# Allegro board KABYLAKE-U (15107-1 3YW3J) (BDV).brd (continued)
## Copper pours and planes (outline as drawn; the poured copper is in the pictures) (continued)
CAGND on TOP: 38.72,23.16 38.64,23.24 38.64,24.77 38.51,24.89 34.83,24.89 34.7,25.02 34.7,26.67 33.94,27.43 33.94,28.07 34.2,28.32 36.61,28.32 36.86,28.07 37.75,28.07 38.26,28.57 38.26,29.34 38.39,29.46 39.4,29.46 39.53,29.34 39.53,27.94 39.28,27.69 39.28,23.24 39.2,23.16 ; 9 cut-outs
CHG_AGND on TOP: 40.67,43.18 40.17,43.69 40.17,44.07 40.42,44.32 40.42,45.21 40.8,45.21 40.93,45.09 40.93,44.32 41.31,43.94 43.21,43.94 43.85,44.58 43.85,46.35 44.1,46.61 45.75,46.61 45.88,46.74 45.88,47.12 46.01,47.24 46.64,47.24 46.77,47.12 46.77,43.69 46.64,43.56 43.21,43.56 42.83,43.18 ; 8 cut-outs
CORE_PLLVDD on TOP: 95.74,101.6 95.61,101.73 95.61,102.57 95.79,102.74 101.13,102.74 101.25,102.62 101.25,101.85 101,101.6 ; 2 cut-outs
DC_19V on TOP: 62.64,31.75 62.39,32 62.39,36.96 63.03,37.59 71.28,37.59 71.41,37.47 71.41,36.45 71.28,36.32 69.88,36.32 69.5,35.94 69.5,31.88 69.38,31.75 ; 4 cut-outs
DC_19V on BOTTOM: 62.77,34.29 62.39,34.67 62.39,35.18 61.37,36.2 61.37,38.23 66.58,38.23 67.22,37.59 71.03,37.59 71.28,37.34 71.28,35.05 70.52,34.29
DCBATOUT on TOP: 147.23,31.11 146.97,31.37 146.97,34.42 148.12,35.56 149.51,35.56 149.89,35.18 149.89,34.8 149.51,34.42 148.24,34.42 147.99,34.16 147.99,32.51 148.24,32.26 148.37,32.26 148.75,31.88 148.75,31.24 148.62,31.11
DCBATOUT on TOP: 34.32,79.12 33.94,79.5 33.94,81.92 29.88,85.98 29.88,132.21 28.23,133.86 16.04,133.86 15.78,134.11 15.78,138.81 16.04,139.06 25.18,139.06 25.56,139.45 25.56,140.97 25.62,141.03 32.68,141.03 32.7,141.02 32.7,136.88 35.09,134.49 35.09,89.41 39.28,85.22 39.28,79.38 39.02,79.12
DCBATOUT on TOP: 40.04,72.9 39.78,73.15 39.78,74.93 39.53,75.18 39.53,75.69 39.28,75.95 39.28,76.58 39.4,76.71 42.32,76.71 43.09,75.95 43.09,73.03 42.96,72.9
DCBATOUT on TOP: 62.64,43.31 62.64,44.58 62.52,44.7 57.69,44.7 57.44,44.96 51.98,44.96 46.9,50.04 41.31,50.04 41.18,50.16 41.18,54.23 41.31,54.36 49.69,54.36 54.01,50.04 63.28,50.04 64.8,48.51 97.95,48.51 98.33,48.13 98.33,45.97 96.17,43.81 71.79,43.81 71.28,43.31
DCBATOUT on TOP: 150.78,45.09 150.66,45.21 150.66,47.12 150.78,47.24 151.67,47.24 151.8,47.12 151.8,45.34 151.54,45.09
DCBATOUT on TOP: 106.71,61.85 106.21,62.36 106.21,67.31 106.59,67.69 120.43,67.69 121.95,69.22 122.97,69.22 126.4,72.64 126.4,73.79 126.78,74.17 126.78,83.06 132.24,83.06 132.37,82.93 142.02,82.93 142.15,82.8 142.15,79.25 139.35,76.45 135.54,76.45 122.59,63.5 111.92,63.5 110.27,61.85
DCBATOUT on TOP: 20.23,165.99 19.97,166.24 19.97,172.09 20.23,172.34 26.83,172.34 27.34,171.83 27.34,166.12 27.21,165.99
DCBATOUT on TOP: 46.01,37.08 45.88,37.21 45.88,40.39 46.01,40.51 47.02,40.51 47.28,40.77 52.74,40.77 52.99,40.51 52.99,39.5 52.87,39.37 49.18,39.37 48.93,39.12 48.93,38.61 48.8,38.48 47.91,38.48 47.53,38.1 47.53,37.21 47.4,37.08 ; 1 cut-out
DCBATOUT on BOTTOM: 63.53,45.21 62.39,46.35 57.44,46.35 56.42,47.37 52.74,47.37 48.67,51.44 45.25,51.44 44.86,51.05 44.86,50.29 44.48,49.91 41.31,49.91 41.18,50.04 41.18,56.26 41.31,56.39 44.99,56.39 45.25,56.64 45.25,64.64 43.59,66.29 43.59,72.64 43.21,73.03 40.04,73.03 39.78,73.28 39.78,74.93 39.53,75.18 39.53,75.56 39.09,76.01 39.02,76.01 35.21,79.82 35.21,82.04 35.47,82.3 42.96,82.3 50.33,74.93 50.33,71.63 49.82,71.12 49.82,66.17 50.45,65.53 50.45,53.21 54.33,49.34 56.99,49.34 58.07,48.26 64.55,48.26 65.06,47.75 65.06,45.47 64.8,45.21 ; 3 cut-outs
DCBATOUT on BOTTOM: 77.76,220.85 77.5,221.11 77.5,224.41 77.76,224.66 81.69,224.66 81.82,224.54 81.82,220.85
DCBATOUT on BOTTOM: 122.84,74.8 121.19,76.45 121.19,78.99 121.57,78.99 124.11,76.45 126.65,76.45 126.78,76.58 126.78,83.06 132.24,83.06 132.37,82.93 132.37,81.92 132.62,81.66 138.08,81.66 138.08,79.12 134.27,75.31 127.67,75.31 127.16,74.8 ; 2 cut-outs
DCBATOUT on BOTTOM: 14.64,136.14 14,136.78 14,149.48 12.99,150.5 12.99,168.91 14.89,170.81 14.89,186.69 14.38,187.2 14.38,201.8 14.77,202.18 14.77,206.38 15.02,206.63 15.02,211.23 17.31,213.51 17.31,218.57 20.48,221.74 33.69,221.74 35.47,223.52 56.04,223.52 56.55,223.01 59.98,223.01 60.23,222.76 60.23,221.23 60.1,221.11 55.41,221.11 55.02,221.49 36.48,221.49 34.7,219.71 21.62,219.71 19.46,217.55 19.46,216.41 19.72,216.15 27.21,216.15 27.59,216.53 34.96,216.53 35.21,216.28 35.21,213.23 35.09,213.11 33.94,213.11 32.93,214.12 28.61,214.12 28.35,213.87 21.39,213.87 17.57,210.05 17.57,209.64 17.56,209.63 17.56,188.85 18.07,188.34 25.69,188.34 28.1,190.75 33.18,190.75 34.45,192.02 45.88,192.02 46.01,191.9 46.01,189.74 45.75,189.48 41.69,189.48 39.53,187.32 28.86,187.32 26.7,185.17 18.7,185.17 18.45,184.91 18.45,171.83 19.08,171.2 24.8,171.2 25.05,170.94 25.05,169.93 25.43,169.54 27.08,169.54 27.34,169.29 27.34,166.12 27.21,165.99 21.24,165.99 19.59,164.34 19.59,136.27 19.46,136.14
DCBATOUT on BOTTOM: 122.08,22.99 121.7,23.37 117.38,23.37 116.81,23.94 108.55,23.94 107.86,24.64 106.21,24.64 104.94,25.91 104.94,29.34 102.9,31.37 102.9,35.05 101.95,36 101.95,43.75 99.98,45.72 95.03,45.72 94.65,46.1 94.65,49.4 98.2,52.96 98.2,60.71 102.65,65.15 109.38,65.15 109.89,64.64 109.89,62.23 109.51,61.85 106.08,61.85 104.17,59.94 104.17,52.07 105.06,51.18 105.06,47.37 110.36,42.08 110.36,29.76 111.67,28.45 116.11,28.45 116.49,28.83 121.45,28.83 121.83,29.21 122.84,29.21 123.99,30.35 127.41,30.35 128.05,30.99 133.38,30.99 133.51,31.11 140.62,31.11 141.89,32.38 148.75,32.38 148.88,32.26 148.88,28.7 148.62,28.45 145.32,28.45 145.07,28.19 141.38,28.19 141.13,27.94 131.61,27.94 131.48,27.81 131.48,26.54 131.22,26.29 127.54,26.29 125.26,24 124.62,24 123.6,22.99
DCBATOUT on L3: 78.01,223.39 78.39,223.01 78.39,220.98 78.27,220.85 76.11,220.85 75.6,221.36 60.36,221.36 60.1,221.11 57.95,221.11 57.44,221.62 57.44,222.76 57.56,222.88 58.33,222.88 58.83,223.39
DCBATOUT_1D35V_VGA on TOP: 117.71,73.1 117.71,73.56 117.48,73.79 117,73.79 117,77.47 116.75,77.72 116.75,79.88 116.87,80.01 119.16,80.01 119.79,79.38 119.79,78.11 119.67,77.98 118.14,77.98 118.04,77.88 118.04,76.58 118.5,76.58 118.52,76.56 118.52,73.79 118.02,73.79 118.02,73.1
DCBATOUT_1D35V_VGA on BOTTOM: 117.18,73.79 117.08,73.89 117.08,76.89 116.75,77.22 116.75,79.88 116.87,80.01 119.16,80.01 119.92,79.25 120.43,79.25 120.56,79.12 120.56,76.33 119.92,76.33 119.54,75.95 119.54,74.04 119.29,73.79 ; 2 cut-outs
DCBATOUT_RT6575_3V on TOP: 128.18,22.61 127.92,22.86 127.92,27.3 128.18,27.56 132.11,27.56 132.37,27.3 132.37,22.73 132.24,22.61
DCBATOUT_RT6575_3V on BOTTOM: 129.57,19.43 129.45,19.56 129.45,20.7 127.8,22.35 127.8,25.65 127.92,25.78 131.61,25.78 131.86,26.04 131.86,27.43 131.99,27.56 133,27.56 133.13,27.43 133.13,19.56 133,19.43 ; 1 cut-out
DCBATOUT_RT6575_5V on TOP: 143.42,22.61 143.29,22.73 143.29,27.43 143.42,27.56 147.23,27.56 147.61,27.18 147.61,25.27 147.23,24.89 147.23,22.86 146.97,22.61
DCBATOUT_RT6575_5V on BOTTOM: 143.92,19.43 143.92,22.35 143.54,22.73 143.54,27.81 148.88,27.81 149,27.69 149,24.51 148.62,24.13 147.48,24.13 147.23,23.88 147.23,19.43 ; 2 cut-outs
DCBATOUT_VCCGTA on TOP: 36.99,209.04 36.74,209.3 36.74,215.01 39.78,218.06 47.53,218.06 47.53,212.6 47.28,212.34 41.56,212.34 38.9,209.68 38.9,209.3 38.64,209.04
DCBATOUT_VCCGTA on BOTTOM: 35.97,212.22 35.72,212.47 35.72,216.79 35.34,217.17 27.72,217.17 27.72,219.33 27.85,219.46 37.88,219.46 38.39,218.95 43.85,218.95 43.98,218.82 43.98,215.39 43.59,215.01 41.94,215.01 41.05,214.12 41.05,212.47 40.8,212.22 ; 2 cut-outs
DCBATOUT_VCCGTB on TOP: 34.58,192.41 34.45,192.53 34.45,197.74 34.58,197.87 41.94,197.87 42.32,198.25 47.53,198.25 47.66,198.12 47.66,192.53 47.53,192.41
DCBATOUT_VCCGTB on BOTTOM: 34.58,192.41 34.32,192.66 34.32,197.74 34.45,197.87 41.44,197.87 43.34,195.96 45.88,195.96 46.13,195.71 46.13,192.66 45.88,192.41
DCBATOUT_VCCSA on TOP: 32.16,164.47 32.04,164.59 32.04,164.97 31.28,165.74 29.5,165.74 29.24,165.99 28.1,165.99 27.97,166.12 27.97,171.45 28.1,171.58 34.58,171.58 34.83,171.32 34.83,164.47
DCBATOUT_VCCSA on BOTTOM: 32.16,164.47 32.04,164.59 32.04,164.97 31.28,165.74 29.5,165.74 29.24,165.99 28.1,165.99 27.97,166.12 27.97,169.42 30.13,171.58 34.58,171.58 34.83,171.32 34.83,164.47
DCBATOUT_VCORE on TOP: 19.34,172.97 19.21,173.1 19.21,178.44 19.46,178.69 33.05,178.69 33.05,173.23 32.93,173.1 25.94,173.1 25.81,172.97
DCBATOUT_VCORE on BOTTOM: 19.46,171.83 19.21,172.09 19.21,177.8 26.58,177.8 27.47,178.69 33.05,178.69 33.05,173.23 32.93,173.1 27.47,173.1 27.15,172.78 27.15,172.15 26.83,171.83
DDR_VDDQ on TOP: 91.16,207.9 91.16,211.2 91.28,211.33 92.87,211.33 93,211.46 93,214.5 93.51,215.01 102.65,215.01 103.28,214.38 103.28,208.41 102.78,207.9
DDR_VDDQ on TOP: 112.56,99.06 112.43,99.19 112.43,100.2 111.41,101.22 111.41,102.62 111.29,102.74 111.29,106.17 111.41,106.3 113.95,106.3 114.08,106.17 114.08,102.11 114.21,101.98 116.11,101.98 116.11,101.73 117,100.84 117,99.44 116.62,99.06
DDR_VDDQ on TOP: 159.29,168.28 159.16,168.4 159.16,169.04 157.2,171.01 155.93,171.01 155.74,171.2 155.74,172.34 155.86,172.47 157.26,172.47 157.39,172.59 158.66,172.59 159.67,171.58 159.67,169.29 159.8,169.16 159.8,168.4 159.67,168.28 ; 2 cut-outs
DDR_VDDQ on BOTTOM: outline of 112 points within 90.33,131.44 156.5,211.71 ; 87 cut-outs
FB_PLLAVDD on L3: 78.14,94.87 78.14,100.58 78.01,100.71 76.61,100.71 76.49,100.58 76.49,100.2 76.61,100.08 77.25,100.08 77.38,99.95 77.38,95.12 77.25,95 76.61,95 76.49,94.87 76.49,94.36 76.61,94.23 81.19,94.23 81.44,93.98 81.44,93.6 81.57,93.47 81.95,93.47 82.08,93.6 82.08,94.49 81.82,94.74 78.27,94.74
GPU_1D05V on TOP: 105.7,99.06 105.7,105.03 106.33,105.66 106.33,106.17 106.46,106.3 107.22,106.3 108.49,105.03 108.49,103.76 109,103.25 110.9,103.25 110.9,100.58 111.16,100.33 111.16,99.19 111.03,99.06 ; 3 cut-outs
ISW_1 on BOTTOM: 41.05,34.42 40.8,34.67 40.8,38.61 40.81,38.62 40.81,39.05 41,39.24 44.1,39.24 44.61,38.73 44.61,34.8 44.48,34.67 42.96,34.67 42.71,34.42
LX on TOP: 33.82,31.24 33.69,31.37 33.69,37.85 33.94,38.1 38.26,38.1 38.64,37.72 38.64,31.62 38.26,31.24
LX on BOTTOM: 33.48,30.28 32.8,30.96 32.8,34.67 32.93,34.8 35.34,34.8 35.47,34.92 35.47,37.47 36.23,38.23 36.23,39.88 37.37,39.88 37.5,39.75 37.5,38.23 37.63,38.1 38.26,38.1 38.64,37.72 38.64,32.51 38.51,32.38 35.72,32.38 35.54,32.21 35.54,30.4 35.42,30.28
MCT_R on TOP: 60.23,9.65 60.1,9.78 60.1,14.1 60.23,14.22 62.52,14.22 62.77,13.97 63.53,13.97 63.79,14.22 63.79,16.89 66.2,16.89 66.2,13.92 65.06,12.78 65.06,10.54 64.42,9.91 62.77,9.91 62.52,9.65 ; 2 cut-outs
MEM_VTT on BOTTOM: 104.68,193.04 99.47,198.25 95.03,198.25 90.84,202.44 90.84,209.17 90.97,209.3 92.11,209.3 92.36,209.04 92.36,202.56 95.66,199.26 100.11,199.26 105.44,193.93 105.44,193.17 105.32,193.04
MEM_VTT on BOTTOM: 141,123.44 140.88,123.57 140.88,123.7 141,123.83 141,126.36 141.13,126.49 141.77,126.49 141.89,126.62 141.89,127.13 142.02,127.25 142.53,127.25 142.78,127 142.78,126.62 143.04,126.36 144.81,126.36 145.58,127.13 149.77,127.13 150.66,126.24 152.05,126.24 152.18,126.36 152.18,126.75 152.31,126.87 152.56,126.87 152.69,126.75 152.69,126.36 152.94,126.11 154.21,126.11 154.34,125.98 154.34,125.22 154.08,124.97 152.18,124.97 151.8,125.35 147.89,125.35 147.25,125.98 145.7,125.98 145.19,125.48 143.29,125.48 142.84,125.03 142.84,123.76 142.53,123.44 ; 5 cut-outs
Net_8 on BOTTOM (solid shape): 118.14,114.05 118.14,108.2 117.13,107.19 115.48,107.19 115.48,114.3 117.89,114.3
P3P3V on BOTTOM: 60.87,57.78 59.72,58.93 57.18,58.93 57.06,59.05 57.06,60.71 56.93,60.83 56.04,60.83 55.02,61.85 54.39,61.85 54.26,61.98 54.26,62.74 54.39,62.87 55.41,62.87 56.17,62.1 60.74,62.1 60.99,61.85 60.99,60.83 61.76,60.07 61.76,57.91 61.63,57.78 ; 4 cut-outs
PEX_PLLVDD_GPU on BOTTOM: 82.46,106.05 81.69,106.81 81.69,108.08 81.31,108.46 81.31,110.11 81.06,110.36 80.3,110.36 80.17,110.49 80.17,111.63 80.04,111.76 77.63,111.76 77.5,111.89 77.5,112.78 77.63,112.9 82.46,112.9 82.58,112.78 82.58,111 82.2,110.62 82.2,109.09 82.46,108.84 82.46,106.81 82.84,106.43 82.84,106.17 82.71,106.05 ; 1 cut-out
PWR_1D0V_PHASE on TOP: 37.75,144.4 37.63,144.53 37.63,148.72 37.37,148.97 37.12,148.97 36.99,149.1 36.99,150.88 36.74,151.13 35.47,151.13 35.34,151.26 35.34,156.72 35.47,156.84 42.58,156.84 42.83,156.59 42.83,147.07 42.71,146.94 41.31,146.94 41.18,146.81 41.18,144.53 41.05,144.4
PWR_1D0V_PHASE on BOTTOM: 37.75,144.4 37.63,144.53 37.63,148.72 37.37,148.97 37.12,148.97 36.99,149.1 36.99,150.88 36.74,151.13 33.94,151.13 33.82,151.26 33.82,156.72 33.94,156.84 42.58,156.84 42.83,156.59 42.83,147.07 42.71,146.94 41.31,146.94 41.18,146.81 41.18,144.53 41.05,144.4
PWR_1D35V_VGA on TOP: 100.49,70.36 100.49,76.2 107.73,76.2 107.98,75.95 107.98,70.48 107.86,70.36
PWR_2D5V_VIN on BOTTOM: 130.72,202.56 130.59,202.69 130.59,203.33 130.72,203.45 132.37,203.45 132.62,203.71 132.62,208.03 132.49,208.15 132.49,211.84 132.62,211.96 136.94,211.96 137.07,211.84 137.07,207.9 136.81,207.65 135.67,207.65 135.42,207.39 135.42,202.95 135.03,202.56
PWR_2D5V_VOUT on BOTTOM: 135.92,198.75 135.8,198.88 135.8,204.72 138.34,204.72 139.23,205.61 140.75,205.61 140.88,205.49 140.88,198.88 140.75,198.75 ; 3 cut-outs
PWR_3D3V_LG2 on BOTTOM: 136.3,21.21 136.3,22.23 137.7,22.23 137.83,22.1 137.83,21.34 137.7,21.21
PWR_3D3V_PH2 on TOP: 131.22,15.88 130.97,16.13 130.97,20.45 131.1,20.57 136.18,20.57 136.43,20.32 136.43,16 136.3,15.88
PWR_3D3V_PH2 on BOTTOM: 137.45,14.1 136.18,15.37 130.08,15.37 129.83,15.62 129.83,16.51 129.95,16.64 130.46,16.64 130.59,16.76 130.59,18.8 130.72,18.92 133.64,18.92 133.76,19.05 133.76,20.57 133.89,20.7 137.19,20.7 137.19,15.75 137.32,15.62 138.84,15.62 138.97,15.49 138.97,14.22 138.84,14.1
PWR_5V_HG1 on BOTTOM: 143.92,16.89 143.54,17.27 143.54,18.8 143.67,18.92 144.81,18.92 144.81,17.02 144.69,16.89
PWR_5V_LG1 on BOTTOM: 141.89,21.21 141.89,22.23 143.16,22.23 143.29,22.1 143.29,21.34 143.16,21.21
PWR_5V_PH1 on TOP: 137.32,14.61 137.19,14.73 137.19,16 137.32,16.13 138.84,16.13 139.48,16.76 139.48,20.45 139.61,20.57 146.59,20.57 146.72,20.45 146.72,15.75 146.46,15.49 139.86,15.49 138.97,14.61
PWR_5V_PH1 on BOTTOM: 139.86,15.49 139.48,15.88 139.48,20.57 139.61,20.7 142.78,20.7 142.91,20.57 142.91,17.02 143.42,16.51 144.94,16.51 145.19,16.76 145.19,17.78 145.07,17.91 145.07,18.92 146.72,18.92 146.72,15.75 146.46,15.49
PWR_CHG_BT_LR on TOP: 37.37,60.45 37.24,60.58 37.24,63.88 37.37,64.01 38.9,64.01 38.9,65.28 39.02,65.41 42.96,65.41 43.09,65.28 43.09,63.75 43.21,63.63 43.85,63.63 43.98,63.5 43.98,60.58 43.85,60.45
PWR_CHG_PHASE on TOP: 37.12,55.12 36.99,55.24 36.99,59.18 37.24,59.44 43.59,59.44 43.72,59.31 43.72,55.24 43.59,55.12
PWR_CHG_PHASE on BOTTOM: 37.12,55.12 36.99,55.24 36.99,60.25 37.85,61.11 42.27,61.11 43.72,59.66 43.72,56.77 40.93,56.77 40.55,56.39 40.55,55.24 40.42,55.12
PWR_DCBATOUT_1D0V on TOP: 25.69,141.86 25.56,141.99 25.56,144.4 27.72,146.56 29.37,146.56 29.75,146.94 29.75,148.59 29.88,148.72 31.78,148.72 32.42,148.08 36.48,148.08 36.61,147.96 36.61,142.49 36.36,142.24 33.31,142.24 32.93,141.86
PWR_DCBATOUT_1D0V on BOTTOM: 25.69,141.86 25.56,141.99 25.56,144.4 27.72,146.56 27.72,148.84 27.59,148.97 27.59,149.99 27.85,150.24 30.89,150.24 31.02,150.11 31.02,149.73 31.15,149.61 31.91,149.61 32.04,149.48 32.04,148.59 32.42,148.21 37.37,148.21 37.37,142.75 37.24,142.62 33.18,142.62 32.42,141.86 ; 1 cut-out
PWR_DCBATOUT_VDDQ on TOP: 87.66,216.92 87.28,217.3 86.01,217.3 85.76,217.55 85.76,219.2 84.36,220.6 84.36,223.65 89.57,223.65 89.82,223.39 89.82,217.17 89.57,216.92 ; 2 cut-outs
PWR_DCBATOUT_VDDQ on BOTTOM: 82.71,219.84 82.33,220.22 82.33,224.41 83.47,224.41 84.11,223.77 89.7,223.77 90.08,224.16 90.08,225.17 90.2,225.3 95.66,225.3 95.92,225.04 95.92,219.96 95.79,219.84
PWR_VCCGT_SWA on TOP: 44.1,205.87 44.1,211.46 47.66,211.46 47.91,211.71 47.91,216.28 54.01,216.28 54.26,216.03 54.26,206.25 53.88,205.87
PWR_VCCGT_SWA on BOTTOM: 44.1,205.87 44.1,211.46 45.75,211.46 46.01,211.71 46.01,214.38 47.91,216.28 54.01,216.28 54.26,216.03 54.26,206.25 53.88,205.87
PWR_VCCGT_SWB on TOP: 47.91,192.66 47.91,196.47 49.69,196.47 49.82,196.6 49.82,199.01 49.56,199.26 44.23,199.26 44.1,199.39 44.1,204.85 54.14,204.85 54.26,204.72 54.26,192.91 54.01,192.66
PWR_VCCGT_SWB on BOTTOM: 48.17,192.66 47.91,192.91 47.91,195.45 46.52,196.85 46.52,199.14 46.39,199.26 44.23,199.26 44.1,199.39 44.1,204.85 54.14,204.85 54.26,204.72 54.26,192.91 54.01,192.66
PWR_VCCSA_DRVH on TOP: 36.74,166.75 36.61,166.88 35.34,166.88 35.34,167.77 35.47,167.89 37.12,167.89 37.37,167.64 37.37,167 37.12,166.75
PWR_VCCSA_DRVL on TOP: 31.28,160.02 31.02,160.27 31.02,160.78 31.15,160.91 33.05,160.91 33.05,160.15 32.93,160.02
PWR_VCCSA_PH on TOP: 33.56,160.02 33.56,163.32 35.21,163.32 35.34,163.45 35.34,166.62 36.36,166.62 36.61,166.37 37.37,166.37 38.01,167 39.4,167 39.53,166.88 39.53,160.15 39.4,160.02
PWR_VCCSA_PH on BOTTOM: 35.47,160.02 35.34,160.15 35.34,166.62 36.36,166.62 36.61,166.37 37.37,166.37 38.01,167 39.4,167 39.53,166.88 39.53,160.15 39.4,160.02
PWR_VCORE_SW on TOP: 33.43,173.61 33.31,173.74 33.31,176.91 35.09,176.91 35.21,177.04 35.21,179.58 35.09,179.71 29.5,179.71 29.5,187.58 29.62,187.71 30.64,187.71 30.77,187.58 30.77,185.42 30.89,185.29 38.64,185.29 39.02,184.91 39.02,175.26 38.9,175.13 38.64,175.13 38.51,175.01 38.51,173.99 38.13,173.61
PWR_VCORE_SW on BOTTOM: 33.31,174.88 33.31,178.18 35.09,178.18 35.21,178.31 35.21,179.58 35.09,179.71 29.5,179.71 29.5,185.17 29.62,185.29 38.64,185.29 39.02,184.91 39.02,175.26 38.64,174.88
PWR_VDDQ_PH on TOP: 93.38,215.65 93,216.03 93,220.73 93.38,221.11 103.41,221.11 103.79,220.73 103.79,216.66 102.78,215.65
PWR_VDDQ_PH on BOTTOM: 93.38,215.65 92.36,216.66 92.11,216.66 91.85,216.92 91.85,217.3 91.98,217.42 91.98,219.46 96.17,219.46 96.43,219.71 96.43,220.73 96.55,220.85 98.59,220.85 98.84,221.11 98.84,223.14 98.97,223.27 104.3,223.27 104.49,223.08 104.49,217.36 102.78,215.65
PWR_VDDQ_VLDOIN on TOP: 87.28,207.9 87.03,208.15 87.03,209.35 86.75,209.63 86.75,211.2 86.88,211.33 89.95,211.33 90.2,211.07 90.2,207.9
PWR_VDDQ_VTT on BOTTOM: 85.12,205.61 84.74,205.99 84.74,208.03 85.5,208.79 85.5,209.4 85.55,209.45 85.55,210.39 85.73,210.39 85.73,209.4 85.76,209.37 85.76,208.91 86.27,208.41 86.52,208.41 86.9,208.79 86.9,209.42 86.52,209.8 86.52,210.19 86.65,210.31 87.28,210.31 88.3,209.3 90.08,209.3 90.2,209.17 90.2,205.61
PWR_VGA_CORE_PHASE1 on TOP: 124.75,79.25 123.99,80.01 122.08,80.01 120.94,81.15 119.79,81.15 119.67,81.28 119.67,91.44 119.92,91.69 130.21,91.69 130.34,91.57 130.34,86.11 126.91,86.11 126.53,85.72 126.53,83.95 126.4,83.82 125,83.82 124.87,83.69 124.87,82.68 125,82.55 126.53,82.55 126.53,79.38 126.4,79.25
PWR_VGA_CORE_PHASE1 on BOTTOM: 123.99,77.98 120.81,81.15 119.79,81.15 119.67,81.28 119.67,91.44 119.92,91.69 130.21,91.69 130.34,91.57 130.34,86.11 126.91,86.11 126.53,85.72 126.53,83.95 126.4,83.82 124.87,83.82 124.75,83.69 124.75,81.41 124.87,81.28 126.53,81.28 126.53,77.98
PWR_VGA_CORE_UGATE1_R on TOP: 124.24,76.96 123.99,77.22 123.99,77.6 123.6,77.98 122.59,77.98 122.59,79.38 122.72,79.5 123.73,79.5 124.49,78.74 126.53,78.74 126.53,77.98 125.38,77.98 125,77.6 125,77.22 124.75,76.96
PWR_VGA_VRAM_LX on TOP: 110.14,71.5 110.02,71.63 110.02,76.07 110.14,76.2 113.7,76.2 113.83,76.07 113.83,74.68 113.95,74.55 115.6,74.55 115.73,74.68 115.73,77.72 116.52,77.72 116.52,76.96 116.75,76.96 116.73,76.95 116.73,76.82 116.75,76.81 116.75,73.79 116.24,73.79 116.03,73.58 116.03,72.67 116.01,72.64 115.6,72.64 114.84,71.88 114.08,71.88 113.7,71.5
PWR_VGA_VRAM_LX on BOTTOM: 110.14,71.5 110.02,71.63 110.02,76.07 110.14,76.2 113.7,76.2 113.83,76.07 113.83,74.68 113.95,74.55 115.6,74.55 115.86,74.8 115.86,76.58 115.98,76.71 116.49,76.71 116.62,76.58 116.62,73.91 116.49,73.79 116.24,73.79 115.98,73.53 115.98,72.77 115.86,72.64 115.6,72.64 114.84,71.88 114.08,71.88 113.7,71.5
RING2 on TOP: 169.32,75.44 168.82,75.95 168.13,75.95 168.05,76.02 168.05,76.53 168.13,76.61 169.17,76.61 169.58,76.2 172.12,76.2 172.25,76.07 172.25,75.56 172.12,75.44
SB3V on TOP: 81.31,139.45 80.68,140.08 80.68,140.84 82.84,140.84 82.96,140.72 82.96,139.95 82.46,139.45
SB3V on TOP: 156.75,187.45 156.5,187.71 156.5,189.74 155.74,190.5 155.74,192.28 155.42,192.6 152.88,192.6 148.88,196.6 148.88,203.45 147.99,204.34 147.99,206.25 149.51,207.77 158.15,207.77 161.2,204.72 165.39,204.72 165.77,204.34 165.77,201.55 165.39,201.17 156.75,201.17 154.72,203.2 151.93,203.2 151.54,202.82 151.54,199.39 157.26,193.68 157.26,192.28 158.66,190.88 159.8,190.88 159.93,190.75 159.93,187.71 159.67,187.45 ; 1 cut-out
SB3V on TOP: 130.84,7.11 129.95,8 127.8,8 127.8,8.64 127.92,8.76 128.3,8.76 128.46,8.92 128.46,10.95 129.83,12.32 129.83,14.73 130.21,15.11 135.54,15.11 135.8,14.86 135.8,10.67 133.89,8.76 133.89,7.11 ; 2 cut-outs
SB3V on TOP: 90.08,122.43 90.08,125.6 89.95,125.73 88.17,125.73 88.04,125.86 88.04,126.36 88.17,126.49 89.06,126.49 89.19,126.62 89.19,128.4 89.31,128.52 93.38,128.52 93.53,128.37 93.53,127.66 93.66,127.53 95,127.53 95.05,127.48 95.05,127 94.93,126.87 93.12,126.87 93,126.75 93,122.43 ; 2 cut-outs
SB3V on TOP: 136.94,105.54 136.69,105.79 136.69,107.06 135.48,108.27 135.42,108.27 135.22,108.46 128.56,108.46 127.8,109.22 110.52,109.22 109.63,110.11 109.63,113.41 110.27,114.05 111.79,114.05 112.43,113.41 112.43,113.16 113.19,112.39 124.75,112.39 125.64,113.28 126.02,113.28 129.57,109.73 135.8,109.73 137.96,107.57 137.96,105.92 137.57,105.54
SB3V on BOTTOM: 131.22,7.37 130.46,8.13 130.46,11.68 130.84,12.06 146.72,12.06 155.99,21.34 155.99,28.19 156.12,28.32 159.8,28.32 160.69,27.43 160.69,23.88 159.55,22.73 159.55,20.19 156.43,17.08 155.58,17.08 153.35,14.86 153.35,11.72 149,7.37 ; 2 cut-outs
SB3V on BOTTOM: 60.74,62.74 60.61,62.87 60.61,64.77 60.87,65.02 61.63,65.02 61.88,64.77 61.88,62.87 61.76,62.74
SB3V on BOTTOM: 137.83,208.03 137.57,208.28 137.57,211.84 137.7,211.96 139.61,211.96 141.13,210.44 141.13,208.28 140.88,208.03
SB3V on BOTTOM: 50.71,5.46 50.07,6.1 49.56,6.1 49.44,6.22 49.44,7.37 49.56,7.49 50.45,7.49 50.58,7.37 50.58,6.86 51.34,6.1 51.34,5.84 50.96,5.46 ; 1 cut-out
SB3V on BOTTOM: 146.72,201.93 146.59,202.06 146.59,206.38 146.97,206.76 146.97,207.26 147.1,207.39 150.66,207.39 150.91,207.14 150.91,202.18 150.66,201.93 ; 6 cut-outs
SB3V on BOTTOM: 41.18,4.45 40.29,5.33 40.29,5.84 40.04,6.1 39.4,6.1 39.28,6.22 39.28,10.54 40.55,10.54 40.55,7.62 41.94,6.22 41.94,5.33 42.32,4.95 42.32,4.57 42.2,4.45 ; 2 cut-outs
SB3V on L3: 96.05,9.02 99.09,9.02 100.24,7.87 111.16,7.87 112.43,9.14 116.75,9.14 117.13,8.76 117.13,8 118.27,6.86 120.94,6.86 121.95,7.87 128.3,7.87 129.19,8.76 133.76,8.76 134.4,9.4 134.4,10.54 133.89,11.05 128.56,11.05 127.16,9.65 121.06,9.65 120.3,8.89 118.91,8.89 118.59,9.21 118.59,9.78 117.44,10.92 111.29,10.92 110.14,9.78 100.49,9.78 99.6,10.67 97.95,10.67 96.55,12.06 95.66,12.06 95.54,11.94 95.54,9.53
SB3V on L4: 139.1,210.82 143.29,210.82 145.07,209.04 150.15,209.04 151.04,208.15 151.04,205.61 150.78,205.36 143.42,205.36 142.02,206.76 140.24,206.76 138.72,208.28 138.72,210.44
SB3V on L4: 148.75,10.16 148.5,10.41 148.5,12.7 155.99,20.19 155.99,28.19 157.13,29.34 162.85,29.34 163.99,30.48 163.99,63.12 165.01,64.14 165.01,67.94 166.02,68.96 166.02,72.39 165.01,73.41 165.01,87.63 165.13,87.76 166.66,87.76 166.91,88.01 166.91,108.33 167.42,108.84 167.42,122.94 168.18,123.7 168.18,124.33 172.37,128.52 172.37,133.86 170.21,136.02 170.21,148.46 170.85,149.1 170.85,154.69 170.09,155.45 168.82,155.45 163.36,160.91 163.36,202.82 163.74,203.2 167.8,203.2 168.18,202.82 168.18,160.53 170.59,158.12 171.99,158.12 174.28,155.83 174.28,148.84 173.64,148.21 173.64,140.97 178.98,135.64 178.98,127.89 171.74,120.65 171.74,91.44 172.25,90.93 172.25,85.09 171.23,84.07 171.23,68.83 168.44,66.04 168.44,60.58 168.05,60.2 168.05,28.45 164.75,25.15 161.58,25.15 160.56,24.13 160.56,18.67 158.66,16.76 154.85,16.76 153.2,15.11 153.2,11.68 151.67,10.16
SB5V on TOP: 95.28,4.57 95.03,4.83 95.03,8.38 94.9,8.51 94.88,8.51 94.83,8.56 92.49,8.56 92.49,9.14 92.87,9.53 95.92,9.53 96.17,9.27 96.17,5.97 96.43,5.71 101,5.71 101.25,5.97 101.25,6.99 101.38,7.11 102.4,7.11 102.52,6.99 102.52,5.33 101.76,4.57
SB5V on TOP: 159.67,119.76 158.91,120.52 158.91,121.67 159.04,121.79 160.43,121.79 160.56,121.67 160.56,120.27 160.05,119.76
SB5V on TOP: 128.18,3.3 128.05,3.43 128.05,5.08 127.8,5.33 127.8,7.49 129.95,7.49 130.72,6.73 139.48,6.73 139.86,7.11 139.86,14.22 140.11,14.48 145.32,14.48 145.45,14.35 145.45,6.35 145.07,5.97 145.07,3.43 144.94,3.3 ; 2 cut-outs
SB5V on BOTTOM: 125.13,2.29 124.87,2.54 124.87,5.08 124.49,5.46 116.87,5.46 116.62,5.71 116.62,7.37 115.98,8 114.71,8 114.33,8.38 114.33,9.78 114.59,10.03 117.76,10.03 118.78,9.02 128.05,9.02 128.68,8.38 128.68,8 129.07,7.62 130.08,7.62 130.97,6.73 135.29,6.73 135.54,6.48 135.54,3.43 134.4,2.29
SB5V on L4: outline of 94 points within 101.13,6.35 168.94,129.92
SB5V on L4: 131.22,6.73 135.54,6.73 135.67,6.6 135.67,3.68 135.54,3.56 131.35,3.56 130.97,3.94 130.97,6.48
SCA_AGND on BOTTOM: 57.31,70.74 57.18,70.87 57.18,76.58 57.31,76.71 59.09,76.71 59.22,76.58 59.22,75.06 58.96,74.8 58.96,73.28 58.83,73.15 58.58,73.15 58.45,73.03 58.45,70.87 58.33,70.74 ; 4 cut-outs
SLEEVE on TOP: 169.68,76.48 169.32,76.83 168.05,76.83 167.8,77.09 167.8,77.22 168.18,77.6 169.45,77.6 169.71,77.34 172.12,77.34 172.25,77.22 172.25,76.58 172.14,76.48 ; 1 cut-out
SP_PLLVDD on TOP: 99.47,99.57 99.22,99.82 99.22,101.22 99.35,101.35 101.51,101.35 101.76,101.6 103.28,101.6 103.44,101.45 104.81,101.45 105.04,101.22 105.04,99.69 104.91,99.57 ; 6 cut-outs
SPKR_L+_C on TOP: 152.81,33.4 152.56,33.66 152.56,34.16 153.2,34.8 153.2,35.69 153.58,36.07 153.58,36.96 152.94,37.59 152.94,38.61 154.34,38.61 154.47,38.48 154.47,34.8 153.07,33.4 ; 2 cut-outs
SPKR_L-_C on TOP: 154.34,33.27 154.08,33.53 154.08,33.78 154.85,34.54 154.85,38.61 156.24,38.61 156.24,37.47 155.86,37.08 155.86,34.04 155.1,33.27 ; 2 cut-outs
SPKR_R+_C on TOP: 160.82,33.78 160.56,34.04 160.56,34.54 160.94,34.92 160.94,38.48 161.07,38.61 162.47,38.61 162.47,37.47 161.83,36.83 161.83,36.07 161.96,35.94 161.96,34.29 161.45,33.78 ; 2 cut-outs
SPKR_R-_C on TOP: 158.91,33.78 158.78,33.91 158.78,34.42 159.16,34.8 159.16,35.56 159.67,36.07 159.67,36.96 159.16,37.47 159.16,38.61 160.56,38.61 160.56,35.05 159.29,33.78 ; 2 cut-outs
USBVCC01 on TOP: 168.94,119.89 168.69,120.14 161.45,120.14 161.32,120.27 161.32,121.79 163.48,121.79 164.82,123.13 164.82,125.29 165.01,125.48 171.74,125.48 173.13,124.08 173.13,120.02 173.01,119.89 ; 2 cut-outs
USBVCC23 on TOP: 90.2,8.56 90.2,9.4 90.46,9.65 90.46,16.51 90.97,17.02 90.97,20.07 91.09,20.19 92.49,20.19 93,20.7 93,40.26 94.52,41.78 102.14,41.78 102.4,41.53 102.4,39.24 102.14,38.99 96.17,38.99 95.16,37.97 95.16,19.56 95.92,18.8 102.14,18.8 102.4,18.54 102.4,16.51 102.14,16.26 93.76,16.26 92.36,14.86 92.36,10.16 91.73,9.53 91.73,8.56 ; 2 cut-outs
V_1P5_HDMI on TOP: 130.59,39.24 130.46,39.37 130.46,41.27 130.61,41.43 134.42,41.43 134.83,41.02 138.84,41.02 138.97,40.89 138.97,40.13 138.84,40.01 138.59,40.01 138.46,40.13 134.78,40.13 134.4,40.51 131.71,40.51 131.35,40.16 131.35,39.37 131.22,39.24 ; 1 cut-out
V_1P5_HDMI on BOTTOM: 137.45,31.37 137.32,31.5 137.32,32.13 137.45,32.26 138.34,32.26 138.46,32.38 138.46,34.8 137.96,35.31 137.96,38.35 138.63,39.03 138.65,39.03 138.67,39.04 138.67,39.93 138.46,40.13 138.46,41.15 138.72,41.4 142.27,41.4 142.4,41.27 142.4,40.26 142.27,40.13 140.11,40.13 139.96,39.98 139.96,38.71 139.86,38.61 139.86,35.43 139.48,35.05 139.48,32.64 139.23,32.38 139.23,31.5 139.1,31.37 ; 1 cut-out
V_1P05_LAN on TOP: 34.07,10.79 33.94,10.92 33.94,11.43 34.2,11.68 34.32,11.68 35.21,12.57 35.21,13.46 35.34,13.59 35.97,13.59 36.1,13.46 36.1,12.32 34.58,10.79 ; 1 cut-out
V_1P05_LAN on BOTTOM: 35.34,10.54 34.7,11.18 34.7,12.7 34.45,12.95 31.53,12.95 31.28,13.21 31.28,16 33.94,18.67 34.58,18.67 35.34,19.43 41.18,19.43 41.82,18.8 41.82,13.84 41.69,13.72 39.91,13.72 39.78,13.84 39.78,14.35 39.91,14.48 40.42,14.48 40.55,14.61 40.55,17.53 40.17,17.91 39.33,17.91 38.69,18.54 35.47,18.54 35.21,18.29 35.21,15.62 35.35,15.48 35.58,15.48 35.59,15.47 36.09,15.47 36.14,15.42 36.14,14.64 35.97,14.48 35.97,12.65 36.18,12.45 38.9,12.45 39.02,12.32 39.02,11.68 38.64,11.3 38.64,10.92 38.26,10.54 ; 8 cut-outs
V_1P05_LAN on L4: 37.75,17.4 41.82,17.4 41.94,17.27 41.94,14.1 40.93,13.08 36.74,13.08 35.21,11.56 35.21,11.05 36.36,9.91 37.37,9.91 37.75,10.29 37.75,10.92 38.39,11.56 38.77,11.56 38.9,11.43 38.9,9.91 37.63,8.64 35.59,8.64 33.31,10.92 33.31,13.72 34.45,14.86 35.21,14.86
V_3P3_A on TOP: 145.7,40.39 145.32,40.77 145.32,44.32 145.58,44.58 146.46,44.58 146.59,44.45 146.59,40.51 146.46,40.39 ; 4 cut-outs
V_3P3_A on BOTTOM: 154.85,25.65 154.72,25.78 154.72,26.29 152.94,28.07 152.94,29.84 150.78,32 150.78,34.42 150.27,34.92 147.35,34.92 147.1,35.18 147.1,35.94 147.23,36.07 150.15,36.07 151.67,34.54 151.67,32.26 153.83,30.1 153.83,28.07 155.35,26.54 155.35,25.78 155.23,25.65
V_3P3_A on BOTTOM: 128.43,11.94 128.3,12.06 128.3,12.83 128.05,13.08 126.4,13.08 126.4,14.1 128.18,14.1 128.68,13.59 129.32,13.59 129.45,13.46 129.45,12.19 129.19,11.94 ; 1 cut-out
V_3P3_LAN on BOTTOM: 41.56,7.24 41.31,7.49 41.31,10.79 41.18,10.92 39.28,10.92 39.02,11.18 39.02,11.43 39.28,11.68 39.28,12.32 39.4,12.45 40.8,12.45 43.09,10.16 43.09,7.75 42.58,7.24 ; 1 cut-out
V_3P3_LAN on L3: 36.86,18.41 38.77,18.41 39.02,18.16 39.02,17.65 38.77,17.4 37.37,17.4 36.36,16.38 36.36,13.72 34.7,12.06 34.7,11.18 35.97,9.91 37.37,9.91 38.18,10.72 38.62,10.72 39.02,11.13 39.02,11.56 39.15,11.68 40.29,11.68 40.42,11.56 40.42,10.54 38.51,8.64 35.72,8.64 33.31,11.05 33.31,12.19 35.34,14.22 35.34,16.89
V_3P3_PCIVAUX on TOP: 118.4,198.12 117.51,199.01 117.51,205.49 117.64,205.61 124.87,205.61 125,205.49 125,200.53 125.13,200.41 145.19,200.41 145.58,200.79 145.58,202.95 145.83,203.2 148.24,203.2 148.5,202.95 148.5,198.25 148.37,198.12 ; 5 cut-outs
V_3P3_PCIVAUX on TOP: 117.51,222.38 117.51,223.39 117.76,223.65 125.51,223.65 125.76,223.39 125.76,222.76 125.64,222.63 121.95,222.63 121.7,222.38 ; 4 cut-outs
V_3P3_PCIVAUX on BOTTOM: 145.58,198.88 145.45,199.01 145.45,201.17 145.58,201.29 150.02,201.29 150.15,201.17 150.15,199.14 149.89,198.88
V_5_CODEC on TOP: 164.63,81.66 164.5,81.79 164.5,83.19 165.01,83.69 165.01,85.47 164.24,86.23 164.24,88.01 164.37,88.14 165.13,88.14 165.39,87.88 165.39,86.87 166.15,86.11 166.15,83.44 165.84,83.13 165.84,81.79 165.72,81.66
V_5_CODEC_R on TOP: 162.59,87.76 162.59,88.52 162.97,88.9 162.97,90.42 163.23,90.68 165.39,90.68 165.51,90.55 165.51,89.41 165.39,89.28 165.39,88.65 165.13,88.39 164.37,88.39 163.99,88.01 163.99,87.88 163.86,87.76 ; 1 cut-out
V_5HDD on TOP: 14.26,191.77 12.35,193.68 10.96,193.68 10.57,194.06 10.57,200.91 10.96,201.29 16.8,201.29 17.05,201.04 17.05,198.37 16.16,197.49 16.16,195.33 16.54,194.94 16.54,193.42 17.05,192.91 18.32,192.91 18.45,192.79 18.45,191.77 ; 4 cut-outs
V_5P0_HDMI_CONN on BOTTOM: 117,38.73 116.49,39.24 115.73,39.24 115.48,39.5 115.48,40.89 114.97,41.4 114.97,41.91 115.1,42.04 117,42.04 118.4,40.64 118.4,38.99 118.14,38.73 ; 2 cut-outs
V_5P0_HDMI_CONN_L on BOTTOM: 116.87,34.54 116.62,34.8 116.62,37.97 116.75,38.1 118.27,38.1 118.4,37.97 118.4,34.8 118.14,34.54
V_19_INV on TOP: 39.66,31.24 39.53,31.37 39.53,38.23 40.17,38.86 41.82,38.86 43.47,40.51 45.25,40.51 45.37,40.39 45.37,39.37 44.99,38.99 44.99,31.88 44.36,31.24
VOUT_INV on TOP: 29.8,37.34 29.29,37.85 27.59,37.85 27.59,39.5 31.66,39.5 31.78,39.37 31.78,37.59 31.53,37.34
VOUT_INV on BOTTOM: 32.55,35.81 32.29,36.07 27.34,36.07 27.34,42.42 31.78,42.42 31.78,39.12 33.05,37.85 34.7,37.85 34.83,37.72 34.83,35.81

Small or netless copper shapes (teardrops, artwork), in the pictures only: 5 on TOP, 5 on BOTTOM, 1 on L5GND

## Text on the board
Ref Des/Silkscreen Bottom: F7:1.5A/6V | F5:2A/6V | F6:1.5A/6V | F4:2A/6V
Ref Des/Silkscreen Top: PASSWORD | RTC_CMOS | SERVICE | _MODE | 1-2 SHORT:ME DISABLE | 1-2 OPEN:DEFAULT | 3-4 SHORT:DEFAULT | 3-4 OPEN:PASSWORD RESET | 5-6 SHORT:RTC_CMOS RESET | 5-6 OPEN:DEFAULT | X1:24MHZ | X5:25MHZ | F3:3A/32V | X4:14.31818MHZ | X3:27MHZ | MO1230 | Dell PN:3YW3J | WWW.DELL.COM | Rev:A00 | X2:32.768KHZ | F1:1.5A/6V | F2:1.5A/6V | Kabylake-U | 15107-1 | 3YW3J | MADE IN TAIWAN | M2xL2.5
User.33: ByImpedance:100.0@_REF_L1=("3.5/10.0(L1)")|_REF_L6=("3.5/10.0(L6)")|Type="DP"|_REF_L4=("4.0/9.0(L4)")|_REF_L3=("4.0/9.0(L3)")|imp="100.0" | ByImpedance:110.0@Type="DP"|_REF_L4=("3.5/13.0(L4)")|_REF_L3=("3.5/13.0(L3)")|imp="110.0" | ByImpedance:27.4@_REF_L1=("12.0(L1)")|_REF_L6=("12.0(L6)")|Type="SE"|_REF_L4=("16.0(L4)")|_REF_L3=("16.0(L3)")|imp="27.4" | ByImpedance:33.0@_REF_L1=("9.0(L1)")|_REF_L6=("9.0(L6)")|Type="SE"|_REF_L4=("12.0(L4)")|_REF_L3=("12.0(L3)")|imp="33.0" | ByImpedance:34.0@_REF_L1=("8.5(L1)")|_REF_L6=("8.5(L6)")|Type="SE"|_REF_L4=("11.5(L4)")|_REF_L3=("11.5(L3)")|imp="34.0" | ByImpedance:35.0@_REF_L1=("8.0(L1)")|_REF_L6=("8.0(L6)")|Type="SE"|_REF_L4=("10.5(L4)")|_REF_L3=("10.5(L3)")|imp="35.0" | ByImpedance:37.5@_REF_L1=("7.0(L1)")|_REF_L6=("7.0(L6)")|Type="SE"|_REF_L4=("9.5(L4)")|_REF_L3=("9.5(L3)")|imp="37.5" | ByImpedance:39.0@_REF_L1=("6.5(L1)")|_REF_L6=("6.5(L6)")|Type="SE"|_REF_L4=("9.0(L4)")|_REF_L3=("9.0(L3)")|imp="39.0" | ByImpedance:40.0@_REF_L1=("6.5(L1)")|_REF_L6=("6.5(L6)")|Type="SE"|_REF_L4=("8.5(L4)")|_REF_L3=("8.5(L3)")|imp="40.0" | ByImpedance:42.0@_REF_L1=("5.5(L1)")|_REF_L6=("5.5(L6)")|Type="SE"|_REF_L4=("7.5(L4)")|_REF_L3=("7.5(L3)")|imp="42.0" | ByImpedance:45.0@_REF_L1=("5.0(L1)")|_REF_L6=("5.0(L6)")|Type="SE"|_REF_L4=("6.5(L4)")|_REF_L3=("6.5(L3)")|imp="45.0" | ByImpedance:48.0@_REF_L1=("4.5(L1)")|_REF_L6=("4.5(L6)")|Type="SE"|_REF_L4=("5.5(L4)")|_REF_L3=("5.5(L3)")|imp="48.0" | ByImpedance:50.0@_REF_L1=("4.0(L1)")|_REF_L6=("4.0(L6)")|Type="SE"|_REF_L4=("5.0(L4)")|_REF_L3=("5.0(L3)")|imp="50.0" | ByImpedance:52.0@_REF_L1=("3.5(L1)")|_REF_L6=("3.5(L6)")|Type="SE"|_REF_L4=("4.5(L4)")|_REF_L3=("4.5(L3)")|imp="52.0" | ByImpedance:55.0@Type="SE"|_REF_L4=("4.0(L4)")|_REF_L3=("4.0(L3)")|imp="55.0" | ByImpedance:65.0@_REF_L1=("8.0/6.0(L1)")|_REF_L6=("8.0/6.0(L6)")|Type="DP"|_REF_L4=("9.0/5.0(L4)")|_REF_L3=("9.0/5.0(L3)")|imp="65.0" | ByImpedance:68.0@_REF_L1=("6.5/4.0(L1)")|_REF_L6=("6.5/4.0(L6)")|Type="DP"|_REF_L4=("7.5/4.0(L4)")|_REF_L3=("7.5/4.0(L3)")|imp="68.0" | ByImpedance:70.0@_REF_L1=("7.0/6.0(L1)")|_REF_L6=("7.0/6.0(L6)")|Type="DP"|_REF_L4=("8.0/6.0(L4)")|_REF_L3=("8.0/6.0(L3)")|imp="70.0" | ByImpedance:72.0@_REF_L1=("7.0/8.0(L1)")|_REF_L6=("7.0/8.0(L6)")|Type="DP"|_REF_L4=("7.0/5.0(L4)")|_REF_L3=("7.0/5.0(L3)")|imp="72.0" | ByImpedance:75.0@_REF_L1=("6.0/6.0(L1)")|_REF_L6=("6.0/6.0(L6)")|Type="DP"|_REF_L4=("7.0/6.0(L4)")|_REF_L3=("7.0/6.0(L3)")|imp="75.0" | ByImpedance:80.0@_REF_L1=("5.0/5.0(L1)")|_REF_L6=("5.0/5.0(L6)")|Type="DP"|_REF_L4=("6.0/6.0(L4)")|_REF_L3=("6.0/6.0(L3)")|imp="80.0" | ByImpedance:85.0@_REF_L1=("5.0/8.0(L1)" "4.0/4.5(L1)")|_REF_L6=("5.0/8.0(L6)" "4.0/4.5(L6)")|Type="DP"|_REF_L4=("5.0/5.5(L4)")|_REF_L3=("5.0/5.5(L3)")|imp="85.0" | ByImpedance:90.0@_REF_L1=("4.0/6.0(L1)")|_REF_L6=("4.0/6.0(L6)")|Type="DP"|_REF_L4=("5.0/8.0(L4)" "4.0/5.0(L4)")|_REF_L3=("5.0/8.0(L3)" "4.0/5.0(L3)")|imp="90.0" | ByImpedance:93.0@_REF_L1=("4.0/8.0(L1)" "3.5/5.5(L1)")|_REF_L6=("4.0/8.0(L6)" "3.5/5.5(L6)")|Type="DP"|_REF_L4=("5.0/9.0(L4)" "4.0/5.5(L4)")|_REF_L3=("5.0/9.0(L3)" "4.0/5.5(L3)")|imp="93.0" | ByImpedance:95.0@_REF_L1=("4.0/10.0(L1)" "3.5/6.0(L1)")|_REF_L6=("4.0/10.0(L6)" "3.5/6.0(L6)")|Type="DP"|_REF_L4=("4.0/6.5(L4)")|_REF_L3=("4.0/6.5(L3)")|imp="95.0" | LayerIndex:nil | Source:6-1.2-7c.xls | artWorks:("_REF_L3" "_REF_L4" "_REF_L6" "_REF_L1") | gtImpOutlineUsed:BOARD GEOMETRY/PANEL_OUTLINE
User.34: Board Accuracy Check,Jun 24 09:18:31 2016,Passed | Dummy-Static-No Shape On Layer Check,Jun 24 09:18:31 2016,1 errors | Split Plane Check,Mar 02 16:25:57 2016,Passed
User.35: GND | 1V_VCCSA | VCC_CORE | 1V_VCCGT
User.36: AGND | GND
User.41: This gerber is just for your reference to find the DP impedance traces in layer L1. | DP IMPEDANCE TABLE: L1 | * - Denotes that this Impedance | is NOT used | IMP(Ohm) | *65.0 | *68.0 | *70.0 | *72.0 | *75.0 | 80.0 | *85.0 | 85.0 | *90.0 | *93.0 | *95.0 | 100.0 | WIDTH(mils) | 8.0/6.0 | 6.5/4.0 | 7.0/6.0 | 7.0/8.0 | 6.0/6.0 | 5.0/5.0 | 5.0/8.0 | 4.0/4.5 | 4.0/6.0 | 4.0/8.0 | 3.5/5.5 | 4.0/10.0 | 3.5/6.0 | 3.5/10.0 | TYPE | DP
User.43: This gerber is just for your reference to find the SE impedance traces in layer L1. | SE IMPEDANCE TABLE: L1 | * - Denotes that this Impedance | is NOT used | IMP(Ohm) | *27.4 | *33.0 | *34.0 | *35.0 | *37.5 | *39.0 | 40.0 | *42.0 | 45.0 | *48.0 | 50.0 | *52.0 | WIDTH(mils) | 12.0 | 9.0 | 8.5 | 8.0 | 7.0 | 6.5 | 5.5 | 5.0 | 4.5 | 4.0 | 3.5 | TYPE | SE
User.45: Note:Refer to DRILL layer for ELLIPSE drill direction | FIGURE | SIZE | 10.0 | 12.0 | 16.0 | 20.0 | 28.0 | 30.0 | 36.0 | 37.0 | 39.0 | 40.0 | 60.0 | 91.0 | 109.0 | 158.0 | 42.0 | 44.0 | 50.0 | 54.0 | 63.0 | 67.0 | 86.0 | 138.0 | 178.0 | 48.0x16.0 | 56.0x24.0 | 60.0x24.0 | 60.0x28.0 | 67.0x28.0 | 67.0x30.0 | 67.0x32.0 | 91.0x28.0 | 156.0x32.0 | 166.0x32.0 | 197.0x178.0 | DRILL CHART: TOP to BOTTOM | ALL UNITS ARE IN MILS | PLATED | NON-PLATED | QTY | 1994 | 2025 | 1057 | 40 | 18 | 14 | 8 | 22 | 15 | 4 | 1 | 5 | 3 | 2 | This gerber is just for your reference to find the DP impedance traces in layer L3. | This gerber is just for your reference to find the DP impedance traces in layer L4. | This gerber is just for your reference to find the DP impedance traces in layer L6. | This gerber is just for your reference to find the SE impedance traces in layer L3. | This gerber is just for your reference to find the SE impedance traces in layer L4. | This gerber is just for your reference to find the SE impedance traces in layer L6. | DP IMPEDANCE TABLE: L3 | DP IMPEDANCE TABLE: L4 | DP IMPEDANCE TABLE: L6 | SE IMPEDANCE TABLE: L3 | SE IMPEDANCE TABLE: L4 | SE IMPEDANCE TABLE: L6 | * - Denotes that this Impedance | is NOT used | Model | Kabylake-U | ECO | 872931 | PCB_NO | 15107 | VER. | Layer | DRILL | L1 | L2GND | L3 | TMASK | TPLACE | TSILK | TSMD | Designer | AKIM | Date | 06/24/2016 | IMP(Ohm) | *27.4 | *65.0 | *33.0 | *68.0 | *34.0 | *70.0 | *35.0 | *72.0 | *37.5 | *75.0 | *39.0 | 80.0 | *40.0 | *85.0 | 85.0 | *42.0 | *90.0 | 45.0 | *48.0 | *93.0 | *52.0 | *95.0 | *55.0 | 100.0 | *110.0 | WIDTH(mils) | 9.0 | 11.5 | 8.5 | 10.5 | 8.0 | 7.0 | 9.5 | 6.5 | 5.5 | 7.5 | 5.0 | 4.5 | 4.0 | 3.5 | 8.0/6.0 | 9.0/5.0 | 6.5/4.0 | 7.5/4.0 | 7.0/6.0 | 7.0/5.0 | 7.0/8.0 | 6.0/6.0 | 5.0/5.0 | 5.0/5.5 | 5.0/8.0 | 4.0/4.5 | 4.0/5.0 | 4.0/6.0 | 4.0/8.0 | 5.0/9.0 | 3.5/5.5 | 4.0/5.5 | 4.0/10.0 | 4.0/6.5 | 3.5/6.0 | 4.0/9.0 | 3.5/10.0 | 3.5/13.0 | TYPE | SE | DP | BMASK | BPLACE | BSILK | BSMD | L4 | L5GND | L6
